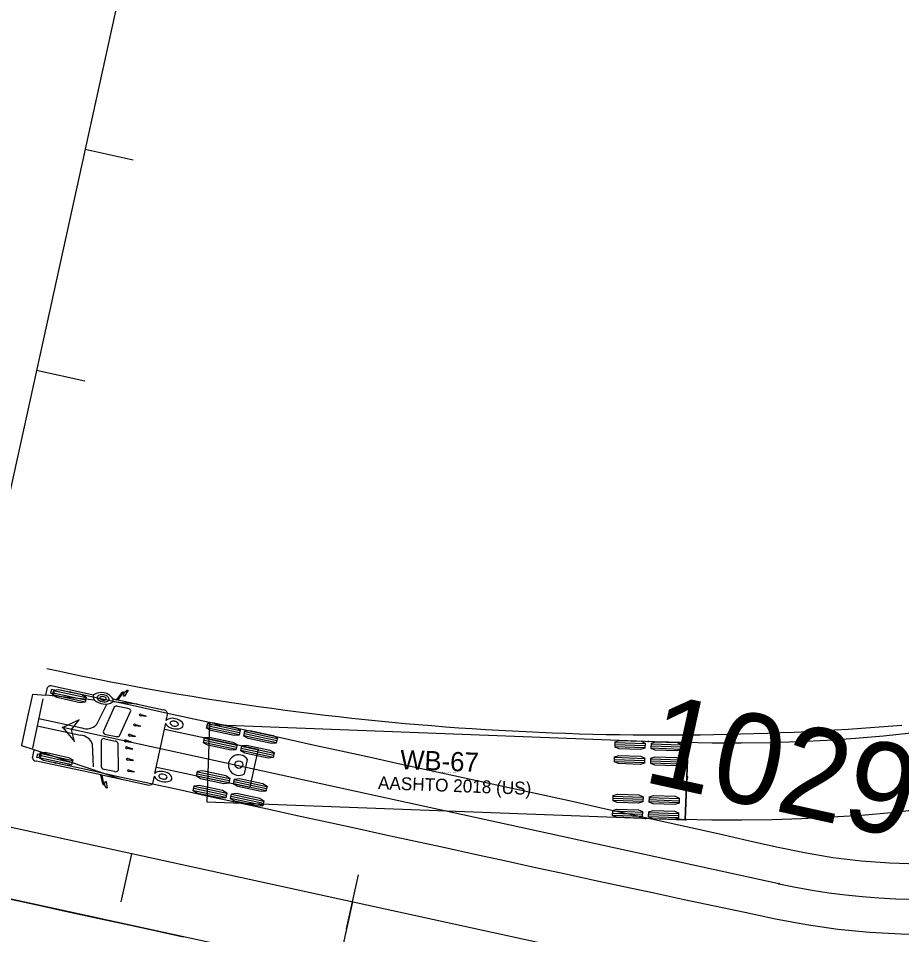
# Model space of a CAD drawing. Extents: x -69 to 14108008, y -6 to 8640172.
# Drawn here: x 14107666.4 to 14107764, y 8639454 to 8639555.2 of the extents above; entities that cross this region are included whole.
import ezdxf

# ---------------------------------------------------------------- set-up
doc = ezdxf.new("R2010")
doc.units = 0
for name, color, linetype in [('Alignment', 7, 'Continuous'), ('AutoTurn', 7, 'Continuous'), ('AutoTurn1', 7, 'Continuous'), ('TextAlignmentLrg', 7, 'Continuous'), ('TextAlignmentSml', 7, 'Continuous')]:
    doc.layers.add(name, color=color, linetype=linetype)

msp = doc.modelspace()

# ---------------------------------------------------------------- linework, layer by layer
at = {"layer": 'Alignment'}
for p, q in [((14107732.61, 8639808.61), (14107547.95, 8638968.47)), ((14107858.63, 8639423.72), (14107657.65, 8639467.55))]:
    msp.add_line(p, q, dxfattribs=at)
msp.add_arc((14107737.69, 8639796.04), 320, 257.6983, 274.7091, dxfattribs=at)
msp.add_arc((14107737.69, 8639796.04), 320, 257.6983, 274.7091, dxfattribs=at)
at = {"layer": 'AutoTurn'}
msp.add_line((14107750.39, 8639459.61), (14107671.27, 8639476.86), dxfattribs=at)
for points in [[(14107652.37, 8639452.09), (14107652.36, 8639452.07), (14107652.43, 8639452.05), (14107657.97, 8639450.85), (14107704.08, 8639440.79), (14107704.98, 8639444.94), (14107705.89, 8639449.1), (14107659.78, 8639459.15), (14107654.24, 8639460.36), (14107654.17, 8639460.37), (14107654.17, 8639460.35)], [(14107665.02, 8639458.01), (14107668.28, 8639457.3), (14107671.54, 8639456.59), (14107674.79, 8639455.88), (14107678.05, 8639455.17), (14107681.31, 8639454.46), (14107684.57, 8639453.75)]]:
    msp.add_lwpolyline(points, dxfattribs=at)
msp.add_arc((14107766.37, 8639532.88), 75, 257.6983, 348.2294, dxfattribs=at)
at = {"layer": 'AutoTurn1'}
for p, q in [((14107670.02, 8639481.05), (14107669.94, 8639480.65)), ((14107669.94, 8639480.65), (14107670.29, 8639480.58)), ((14107670.37, 8639480.98), (14107670.02, 8639481.05)), ((14107670.15, 8639481.45), (14107674.69, 8639480.48)), ((14107670.22, 8639480.71), (14107673.8, 8639479.93)), ((14107670.27, 8639480.94), (14107673.85, 8639480.16)), ((14107670.29, 8639480.58), (14107670.37, 8639480.98)), ((14107678.05, 8639480.69), (14107678.06, 8639480.71)), ((14107678.06, 8639480.71), (14107678.08, 8639480.73)), ((14107669.08, 8639480.02), (14107667.92, 8639474.58)), ((14107674.8, 8639479.9), (14107669.4, 8639480.42)), ((14107670.17, 8639480.49), (14107673.75, 8639479.71)), ((14107679.55, 8639479.44), (14107676.76, 8639479.71)), ((14107677.35, 8639479.91), (14107677.25, 8639479.93)), ((14107674.99, 8639477.16), (14107676.13, 8639479.45)), ((14107676.97, 8639479.11), (14107675.73, 8639476.38)), ((14107678.48, 8639478.96), (14107677.37, 8639479.2)), ((14107677.55, 8639475.95), (14107678.8, 8639478.69)), ((14107668.62, 8639477.85), (14107673.4, 8639476.83)), ((14107680.45, 8639478.07), (14107679.9, 8639478.14)), ((14107679.94, 8639478.31), (14107680.47, 8639478.15)), ((14107680.47, 8639478.15), (14107680.45, 8639478.07)), ((14107682.86, 8639478.45), (14107682.68, 8639477.63)), ((14107668.45, 8639477.04), (14107673.23, 8639476.02)), ((14107750.39, 8639459.61), (14107671.27, 8639476.86)), ((14107679.82, 8639476.96), (14107679.27, 8639477.03)), ((14107679.31, 8639477.2), (14107679.84, 8639477.04)), ((14107679.84, 8639477.04), (14107679.82, 8639476.96)), ((14107682.48, 8639476.68), (14107681.57, 8639472.45)), ((14107687.18, 8639476.85), (14107690.77, 8639476.08)), ((14107687.23, 8639477.07), (14107690.82, 8639476.31)), ((14107687.28, 8639477.3), (14107690.87, 8639476.53)), ((14107675.94, 8639475.6), (14107677.05, 8639475.36)), ((14107676.05, 8639476.1), (14107677.16, 8639475.87)), ((14107679.24, 8639475.84), (14107678.69, 8639475.91)), ((14107678.73, 8639476.08), (14107679.26, 8639475.92)), ((14107679.26, 8639475.92), (14107679.24, 8639475.84)), ((14107686.94, 8639475.68), (14107690.52, 8639474.92)), ((14107691.29, 8639475.97), (14107694.88, 8639475.21)), ((14107691.34, 8639476.2), (14107694.93, 8639475.43)), ((14107691.39, 8639476.42), (14107694.97, 8639475.65)), ((14107674.54, 8639475.07), (14107674.64, 8639472.52)), ((14107675.56, 8639472.48), (14107675.54, 8639475.48)), ((14107677.38, 8639475.12), (14107677.39, 8639472.12)), ((14107678.79, 8639475.21), (14107678.24, 8639475.29)), ((14107678.28, 8639475.45), (14107678.81, 8639475.3)), ((14107678.43, 8639474.69), (14107678.96, 8639474.54)), ((14107678.81, 8639475.3), (14107678.79, 8639475.21)), ((14107686.84, 8639475.24), (14107690.43, 8639474.47)), ((14107686.89, 8639475.46), (14107690.47, 8639474.69)), ((14107691, 8639474.58), (14107694.58, 8639473.82)), ((14107691.04, 8639474.81), (14107694.63, 8639474.04)), ((14107732.29, 8639474.76), (14107735.59, 8639474.64)), ((14107732.3, 8639474.99), (14107735.6, 8639474.87)), ((14107732.31, 8639475.22), (14107735.61, 8639475.09)), ((14107736.29, 8639474.61), (14107739.59, 8639474.48)), ((14107736.3, 8639474.84), (14107739.6, 8639474.71)), ((14107736.31, 8639475.07), (14107739.61, 8639474.94)), ((14107740.32, 8639475.14), (14107740, 8639466.65)), ((14107677.78, 8639471.13), (14107668.11, 8639474.38)), ((14107668.42, 8639473.54), (14107668.51, 8639473.95)), ((14107668.51, 8639473.95), (14107668.85, 8639473.87)), ((14107668.69, 8639473.56), (14107672.27, 8639472.78)), ((14107668.74, 8639473.79), (14107672.32, 8639473.01)), ((14107668.85, 8639473.87), (14107668.77, 8639473.47)), ((14107668.79, 8639474.01), (14107672.37, 8639473.23)), ((14107678.94, 8639474.45), (14107678.4, 8639474.53)), ((14107678.96, 8639474.54), (14107678.94, 8639474.45)), ((14107690.95, 8639474.36), (14107694.53, 8639473.59)), ((14107732.25, 8639473.57), (14107735.55, 8639473.45)), ((14107668.77, 8639473.47), (14107668.42, 8639473.54)), ((14107679.02, 8639473.19), (14107678.44, 8639473.27)), ((14107678.48, 8639473.44), (14107679.03, 8639473.28)), ((14107679.03, 8639473.28), (14107679.02, 8639473.19)), ((14107691.34, 8639471.75), (14107691.68, 8639473.33)), ((14107732.23, 8639473.11), (14107735.53, 8639472.99)), ((14107732.24, 8639473.34), (14107735.54, 8639473.22)), ((14107736.23, 8639472.96), (14107739.53, 8639472.84)), ((14107736.24, 8639473.19), (14107739.54, 8639473.06)), ((14107736.25, 8639473.42), (14107739.54, 8639473.29)), ((14107675.58, 8639471.59), (14107675.48, 8639471.62)), ((14107676.99, 8639472), (14107675.88, 8639472.24)), ((14107679.14, 8639471.92), (14107678.59, 8639472)), ((14107678.63, 8639472.16), (14107679.16, 8639472.01)), ((14107679.16, 8639472.01), (14107679.14, 8639471.92)), ((14107686.05, 8639471.54), (14107689.64, 8639470.77)), ((14107686.1, 8639471.76), (14107689.68, 8639470.99)), ((14107686.15, 8639471.98), (14107689.73, 8639471.22)), ((14107675.9, 8639470.6), (14107675.89, 8639470.57)), ((14107675.89, 8639470.57), (14107675.9, 8639470.54)), ((14107681.37, 8639471.5), (14107681.2, 8639470.67)), ((14107690.16, 8639470.66), (14107693.74, 8639469.89)), ((14107690.21, 8639470.88), (14107693.79, 8639470.12)), ((14107690.25, 8639471.11), (14107693.84, 8639470.34)), ((14107740.23, 8639470.9), (14107740.16, 8639470.9)), ((14107740.22, 8639470.63), (14107740.21, 8639470.36)), ((14107740.22, 8639470.64), (14107740.24, 8639471.16)), ((14107740.25, 8639471.43), (14107740.24, 8639471.16)), ((14107685.71, 8639469.92), (14107689.29, 8639469.16)), ((14107685.75, 8639470.15), (14107689.34, 8639469.38)), ((14107685.8, 8639470.37), (14107689.39, 8639469.6)), ((14107689.81, 8639469.04), (14107693.4, 8639468.28)), ((14107689.86, 8639469.27), (14107693.45, 8639468.5)), ((14107689.91, 8639469.49), (14107693.49, 8639468.73)), ((14107732.07, 8639468.83), (14107735.37, 8639468.71)), ((14107732.08, 8639469.06), (14107735.38, 8639468.94)), ((14107732.09, 8639469.29), (14107735.38, 8639469.17)), ((14107736.07, 8639468.68), (14107739.36, 8639468.56)), ((14107736.08, 8639469.14), (14107739.38, 8639469.01)), ((14107736.08, 8639468.91), (14107739.37, 8639468.78)), ((14107732.02, 8639467.64), (14107735.32, 8639467.52)), ((14107736.02, 8639467.49), (14107739.32, 8639467.36)), ((14107732.01, 8639467.18), (14107735.3, 8639467.06)), ((14107732.02, 8639467.41), (14107735.31, 8639467.29)), ((14107736, 8639467.03), (14107739.3, 8639466.91)), ((14107736.01, 8639467.26), (14107739.31, 8639467.14))]:
    msp.add_line(p, q, dxfattribs=at)
for points in [[(14107667.93, 8639473.53), (14107668.11, 8639474.37), (14107668.11, 8639474.38), (14107666.75, 8639474.83), (14107666.76, 8639474.9), (14107667.36, 8639477.7), (14107667.96, 8639480.5), (14107667.97, 8639480.56), (14107669.4, 8639480.42), (14107669.4, 8639480.43), (14107669.58, 8639481.27)], [(14107765.78, 8639461.78), (14107762.62, 8639461.87), (14107759.47, 8639462.11), (14107756.34, 8639462.48), (14107753.22, 8639463), (14107750.13, 8639463.65), (14107747, 8639464.36), (14107743.84, 8639465.07), (14107740.67, 8639465.78), (14107737.49, 8639466.49), (14107734.3, 8639467.19), (14107731.1, 8639467.89), (14107727.88, 8639468.6), (14107724.67, 8639469.3), (14107721.44, 8639470.01), (14107718.21, 8639470.71), (14107714.98, 8639471.42), (14107711.74, 8639472.13), (14107708.5, 8639472.83), (14107705.26, 8639473.54), (14107702.02, 8639474.25), (14107698.77, 8639474.96), (14107695.52, 8639475.67), (14107692.27, 8639476.37), (14107689.02, 8639477.08), (14107685.77, 8639477.79), (14107682.52, 8639478.5), (14107679.27, 8639479.21), (14107676.01, 8639479.92), (14107672.76, 8639480.63), (14107672.11, 8639480.77)], [(14107676.83, 8639480.02), (14107677.25, 8639479.93), (14107677.26, 8639479.94), (14107677.85, 8639480.74)], [(14107677.99, 8639480.75), (14107678.08, 8639480.73), (14107678.08, 8639480.73), (14107678.38, 8639481), (14107678.38, 8639481), (14107678.5, 8639480.97), (14107678.5, 8639480.97), (14107678.1, 8639480.32), (14107678, 8639480.34), (14107678.05, 8639480.69), (14107678.05, 8639480.69), (14107677.97, 8639480.7), (14107677.97, 8639480.7), (14107677.97, 8639480.7), (14107677.93, 8639480.7), (14107677.93, 8639480.7), (14107677.35, 8639479.91), (14107682.41, 8639478.83)], [(14107671.27, 8639476.86), (14107672.56, 8639475.33), (14107672.25, 8639476.65), (14107673.08, 8639477.71), (14107671.27, 8639476.86)], [(14107682.62, 8639477.35), (14107682.48, 8639476.68), (14107682.71, 8639476.63), (14107692.85, 8639474.47), (14107692.39, 8639472.35), (14107691.94, 8639470.23), (14107681.81, 8639472.4), (14107681.57, 8639472.45), (14107681.43, 8639471.77)], [(14107740.39, 8639475.12), (14107740.39, 8639475.14), (14107740.32, 8639475.14), (14107734.66, 8639475.36), (14107687.5, 8639477.15), (14107687.34, 8639472.9), (14107687.18, 8639468.66), (14107734.34, 8639466.87), (14107740, 8639466.65), (14107740.07, 8639466.65), (14107740.07, 8639466.67)], [(14107765.02, 8639476.24), (14107761.96, 8639475.9), (14107758.86, 8639475.63), (14107755.74, 8639475.43), (14107752.59, 8639475.27), (14107749.42, 8639475.18), (14107746.24, 8639475.13), (14107743.04, 8639475.14), (14107739.83, 8639475.19), (14107736.61, 8639475.29), (14107735.97, 8639475.31)], [(14107740.31, 8639471.16), (14107740.32, 8639471.42), (14107740.32, 8639471.42), (14107740.25, 8639471.43), (14107740.25, 8639471.46), (14107740.39, 8639475.09), (14107740.39, 8639475.1)], [(14107675.7, 8639470.63), (14107675.48, 8639471.61), (14107675.47, 8639471.62), (14107668.37, 8639473.13)], [(14107767.4, 8639453.99), (14107763.9, 8639454.03), (14107760.41, 8639454.21), (14107756.92, 8639454.56), (14107753.46, 8639455.05), (14107750.02, 8639455.7), (14107746.64, 8639456.41), (14107743.27, 8639457.12), (14107739.93, 8639457.83), (14107736.6, 8639458.55), (14107733.28, 8639459.26), (14107729.97, 8639459.98), (14107726.66, 8639460.7), (14107723.37, 8639461.41), (14107720.08, 8639462.13), (14107716.8, 8639462.84), (14107713.52, 8639463.56), (14107710.24, 8639464.27), (14107706.97, 8639464.98), (14107703.7, 8639465.69), (14107700.44, 8639466.41), (14107697.17, 8639467.12), (14107693.91, 8639467.83), (14107690.64, 8639468.54), (14107687.38, 8639469.25), (14107684.12, 8639469.96), (14107680.86, 8639470.68), (14107677.6, 8639471.39), (14107674.34, 8639472.1), (14107671.08, 8639472.81), (14107670.43, 8639472.95)], [(14107680.64, 8639470.51), (14107675.58, 8639471.59), (14107675.79, 8639470.63), (14107675.79, 8639470.63), (14107675.82, 8639470.61), (14107675.82, 8639470.61), (14107675.82, 8639470.61), (14107675.9, 8639470.6), (14107675.9, 8639470.6), (14107675.99, 8639470.93), (14107676.09, 8639470.91), (14107676.19, 8639470.16), (14107676.19, 8639470.15), (14107676.07, 8639470.18), (14107676.07, 8639470.18), (14107675.9, 8639470.54), (14107675.9, 8639470.54), (14107675.82, 8639470.56)], [(14107740.07, 8639466.69), (14107740.07, 8639466.7), (14107740.21, 8639470.33), (14107740.21, 8639470.36), (14107740.28, 8639470.36), (14107740.28, 8639470.36), (14107740.29, 8639470.63)], [(14107766.04, 8639467.8), (14107762.79, 8639467.44), (14107759.52, 8639467.16), (14107756.23, 8639466.94), (14107752.93, 8639466.78), (14107749.62, 8639466.68), (14107746.3, 8639466.63), (14107742.97, 8639466.64), (14107739.64, 8639466.69), (14107736.31, 8639466.79), (14107735.65, 8639466.82)]]:
    msp.add_lwpolyline(points, dxfattribs=at)
for points in [[(14107670.16, 8639480.43), (14107670.28, 8639480.99), (14107670.82, 8639481.05), (14107673.4, 8639480.49), (14107673.86, 8639480.21), (14107673.74, 8639479.65), (14107673.2, 8639479.59), (14107670.62, 8639480.16)], [(14107671.27, 8639476.86), (14107672.56, 8639475.33), (14107672.25, 8639476.65), (14107673.08, 8639477.71)], [(14107687.17, 8639476.79), (14107687.29, 8639477.35), (14107687.83, 8639477.41), (14107690.41, 8639476.86), (14107690.88, 8639476.59), (14107690.76, 8639476.03), (14107690.22, 8639475.97), (14107687.64, 8639476.52)], [(14107686.83, 8639475.18), (14107686.95, 8639475.74), (14107687.49, 8639475.8), (14107690.07, 8639475.25), (14107690.53, 8639474.97), (14107690.41, 8639474.41), (14107689.88, 8639474.35), (14107687.29, 8639474.9)], [(14107691.28, 8639475.92), (14107691.4, 8639476.48), (14107691.94, 8639476.54), (14107694.52, 8639475.99), (14107694.99, 8639475.71), (14107694.87, 8639475.15), (14107694.33, 8639475.09), (14107691.75, 8639475.64)], [(14107690.94, 8639474.3), (14107691.06, 8639474.86), (14107691.59, 8639474.92), (14107694.17, 8639474.37), (14107694.64, 8639474.1), (14107694.52, 8639473.54), (14107693.98, 8639473.48), (14107691.4, 8639474.03)], [(14107732.29, 8639474.7), (14107732.31, 8639475.28), (14107732.78, 8639475.43), (14107735.16, 8639475.34), (14107735.61, 8639475.15), (14107735.59, 8639474.58), (14107735.12, 8639474.42), (14107732.75, 8639474.52)], [(14107736.29, 8639474.55), (14107736.31, 8639475.12), (14107736.78, 8639475.28), (14107739.15, 8639475.19), (14107739.61, 8639475), (14107739.59, 8639474.43), (14107739.12, 8639474.27), (14107736.74, 8639474.36)], [(14107668.68, 8639473.51), (14107668.8, 8639474.07), (14107669.34, 8639474.13), (14107671.92, 8639473.56), (14107672.38, 8639473.29), (14107672.26, 8639472.73), (14107671.72, 8639472.67), (14107669.14, 8639473.23)], [(14107732.23, 8639473.06), (14107732.25, 8639473.63), (14107732.72, 8639473.78), (14107735.09, 8639473.69), (14107735.55, 8639473.5), (14107735.53, 8639472.93), (14107735.06, 8639472.78), (14107732.68, 8639472.87)], [(14107736.23, 8639472.9), (14107736.25, 8639473.48), (14107736.72, 8639473.63), (14107739.09, 8639473.54), (14107739.55, 8639473.35), (14107739.52, 8639472.78), (14107739.06, 8639472.62), (14107736.68, 8639472.71)], [(14107686.04, 8639471.48), (14107686.16, 8639472.04), (14107686.7, 8639472.1), (14107689.28, 8639471.55), (14107689.74, 8639471.27), (14107689.62, 8639470.71), (14107689.09, 8639470.65), (14107686.5, 8639471.2)], [(14107690.15, 8639470.6), (14107690.26, 8639471.16), (14107690.8, 8639471.22), (14107693.38, 8639470.67), (14107693.85, 8639470.4), (14107693.73, 8639469.84), (14107693.19, 8639469.78), (14107690.61, 8639470.33)], [(14107685.69, 8639469.87), (14107685.81, 8639470.43), (14107686.35, 8639470.49), (14107688.93, 8639469.94), (14107689.4, 8639469.66), (14107689.28, 8639469.1), (14107688.74, 8639469.04), (14107686.16, 8639469.59)], [(14107689.8, 8639468.99), (14107689.92, 8639469.55), (14107690.46, 8639469.61), (14107693.04, 8639469.06), (14107693.51, 8639468.78), (14107693.39, 8639468.22), (14107692.85, 8639468.16), (14107690.27, 8639468.71)], [(14107732.07, 8639468.78), (14107732.09, 8639469.35), (14107732.56, 8639469.5), (14107734.93, 8639469.41), (14107735.39, 8639469.22), (14107735.36, 8639468.65), (14107734.9, 8639468.5), (14107732.52, 8639468.59)], [(14107736.06, 8639468.62), (14107736.09, 8639469.2), (14107736.55, 8639469.35), (14107738.93, 8639469.26), (14107739.38, 8639469.07), (14107739.36, 8639468.5), (14107738.89, 8639468.34), (14107736.52, 8639468.43)], [(14107732, 8639467.13), (14107732.03, 8639467.7), (14107732.49, 8639467.85), (14107734.87, 8639467.76), (14107735.32, 8639467.57), (14107735.3, 8639467), (14107734.83, 8639466.85), (14107732.46, 8639466.94)], [(14107736, 8639466.98), (14107736.02, 8639467.55), (14107736.49, 8639467.7), (14107738.87, 8639467.61), (14107739.32, 8639467.42), (14107739.3, 8639466.85), (14107738.83, 8639466.7), (14107736.46, 8639466.79)]]:
    msp.add_lwpolyline(points, close=True, dxfattribs=at)
for centre, radius in [((14107672.11, 8639480.77), 0.0417), ((14107671.27, 8639476.86), 0.0417), ((14107735.97, 8639475.31), 0.0417), ((14107740.43, 8639475.11), 0.0266), ((14107670.43, 8639472.95), 0.0417), ((14107690.73, 8639472.77), 0.424), ((14107735.65, 8639466.82), 0.0417), ((14107740.11, 8639466.68), 0.0266), ((14107750.39, 8639459.61), 0.0417), ((14107750.39, 8639459.61), 0.0417)]:
    msp.add_circle(centre, radius, dxfattribs=at)
for centre, radius, start, end in [((14107766.37, 8639532.88), 75, 257.6983, 348.2294), ((14107669.98, 8639480.99), 0.486, 69.5324, 145.4835), ((14107675.53, 8639479.2), 1.53, 32.4392, 123.4482), ((14107677.91, 8639480.74), 0.0522, 76.829, 181.6837), ((14107677.91, 8639480.68), 0.108, 40.9228, 87.1053), ((14107675.06, 8639480.23), 0.425, 146.0094, 232.5457), ((14107675.94, 8639481.16), 1.7, 227.8671, 263.7752), ((14107675.58, 8639479.87), 0.634, 68.5303, 144.532), ((14107675.43, 8639480.21), 0.366, 175.9988, 248.4798), ((14107675.9, 8639480.89), 1.19, 239.0776, 274.967), ((14107675.59, 8639480.07), 0.223, 85.1813, 154.7838), ((14107675.54, 8639480.15), 0.158, 172.9177, 234.4304), ((14107675.81, 8639480.46), 0.575, 231.0216, 267.5919), ((14107675.65, 8639479.7), 0.589, 50.702, 93.6847), ((14107676.02, 8639480.57), 1.14, 256.651, 310.4535), ((14107675.85, 8639480.15), 0.263, 256.8813, 330.7833), ((14107675.62, 8639479.45), 1.03, 50.7701, 79.1566), ((14107676.01, 8639480.14), 0.44, 269.7407, 333.5535), ((14107675.91, 8639480.03), 0.17, 355.6155, 49.6798), ((14107676.09, 8639479.98), 0.317, 353.7966, 55.389), ((14107676.49, 8639479.93), 0.347, 320.2736, 15.0842), ((14107677.24, 8639478.83), 0.387, 70.3816, 133.6136), ((14107678.47, 8639478.63), 0.332, 10.603, 89.025), ((14107682.28, 8639478.22), 0.619, 22.1067, 77.9485), ((14107679.86, 8639478.18), 0.157, 57.2908, 144.4005), ((14107679.9, 8639478.33), 0.184, 199.1012, 270.9933), ((14107683.39, 8639476.74), 1.14, 73.5252, 128.3165), ((14107683.46, 8639476.43), 1.42, 42.9504, 80.0183), ((14107673.93, 8639478.25), 1.52, 249.5265, 313.9539), ((14107679.22, 8639477.07), 0.157, 57.2908, 144.4005), ((14107679.27, 8639477.22), 0.184, 199.1012, 270.9933), ((14107683.31, 8639477.6), 0.729, 199.624, 242.1379), ((14107683.85, 8639478.44), 1.73, 239.3213, 264.1198), ((14107683.31, 8639477.35), 0.169, 129.3934, 229.5121), ((14107683.71, 8639477.75), 0.732, 226.5382, 272.7726), ((14107683.49, 8639477.04), 0.522, 75.7769, 122.9411), ((14107683.54, 8639476.88), 0.664, 44.8209, 83.0426), ((14107683.86, 8639477.84), 1.14, 260.6617, 302.1825), ((14107683.78, 8639477.38), 0.362, 264.6089, 313.6499), ((14107683.89, 8639477.23), 0.172, 320.4942, 47.6448), ((14107684.25, 8639477.15), 0.346, 307.5407, 44.5537), ((14107673.13, 8639474.5), 1.52, 21.939, 86.3664), ((14107675.8, 8639475.34), 0.296, 60.93, 151.2277), ((14107676.03, 8639476.4), 0.296, 184.6652, 274.9629), ((14107677.29, 8639476.23), 0.387, 250.3841, 313.6111), ((14107678.64, 8639475.94), 0.157, 57.2908, 144.4005), ((14107678.69, 8639476.1), 0.184, 199.1012, 270.9933), ((14107677.02, 8639474.98), 0.387, 22.2817, 85.5088), ((14107678.19, 8639475.32), 0.157, 57.2908, 144.4005), ((14107678.22, 8639475.44), 0.157, 191.4924, 278.6021), ((14107678.35, 8639474.53), 0.184, 64.8996, 136.7916), ((14107678.37, 8639474.69), 0.157, 191.4924, 278.6021), ((14107742.41, 8639475.04), 2.02, 177.8272, 178.511), ((14107690.72, 8639472.71), 1.14, 32.9464, 302.9464), ((14107668.4, 8639473.62), 0.486, 190.4094, 266.3605), ((14107678.43, 8639473.27), 0.184, 64.8996, 136.7916), ((14107678.45, 8639473.42), 0.157, 191.4924, 278.6021), ((14107675.91, 8639472.62), 0.387, 202.2793, 265.5113), ((14107677.12, 8639472.31), 0.332, 246.8678, 325.2898), ((14107678.55, 8639472), 0.184, 64.8996, 136.7916), ((14107678.57, 8639472.15), 0.157, 191.4924, 278.6021), ((14107681.96, 8639471.27), 0.729, 93.7549, 136.2689), ((14107682.06, 8639471.5), 0.169, 106.3808, 206.4995), ((14107682.11, 8639470.28), 1.73, 71.7731, 96.5716), ((14107682.26, 8639470.97), 0.732, 63.1203, 109.3547), ((14107682.47, 8639471.28), 0.362, 22.243, 71.284), ((14107682.36, 8639470.82), 1.14, 33.7104, 75.2311), ((14107675.74, 8639470.61), 0.0522, 154.2092, 259.0638), ((14107675.77, 8639470.66), 0.108, 248.7876, 294.9701), ((14107680.77, 8639471.12), 0.619, 257.9444, 313.7861), ((14107682.38, 8639472.02), 1.14, 207.5764, 262.3677), ((14107682.35, 8639471.71), 0.522, 212.9518, 260.1159), ((14107682.57, 8639472.27), 1.42, 255.8746, 292.9424), ((14107682.46, 8639471.83), 0.664, 252.8503, 291.072), ((14107682.64, 8639471.37), 0.172, 288.248, 15.3986), ((14107683, 8639471.29), 0.346, 291.3391, 28.3522), ((14107740.26, 8639470.63), 0.0352, 357.8525, 176.8529), ((14107740.26, 8639470.63), 0.0353, 181.1634, 359.5131), ((14107740.28, 8639471.16), 0.0354, 2.1188, 174.3042), ((14107740.28, 8639471.16), 0.0352, 178.8016, 357.802), ((14107740.11, 8639466.68), 0.0363, 196.9047, 158.066)]:
    msp.add_arc(centre, radius, start, end, dxfattribs=at)
for centre, major_axis, start_param, end_param in [((14107677.92, 8639480.74), (-0.0765, 0.0163), 0.569648, 1.840391), ((14107677.92, 8639480.74), (-0.0765, 0.0163), 2.398717, 3.668019), ((14107675.76, 8639470.6), (0.0765, -0.0163), 1.301202, 2.571945), ((14107675.76, 8639470.6), (-0.0765, 0.0163), 2.615166, 3.884468)]:
    msp.add_ellipse(centre, major_axis=major_axis, ratio=0.544872, start_param=start_param, end_param=end_param, dxfattribs=at)
at = {"layer": 'TextAlignmentLrg'}
msp.add_line((14107703.29, 8639457.6), (14107702.12, 8639452.26), dxfattribs=at)
at = {"layer": 'TextAlignmentSml'}
for p, q in [((14107673.74, 8639540.75), (14107679.07, 8639539.58)), ((14107668.37, 8639516.34), (14107673.7, 8639515.16)), ((14107678.86, 8639462.92), (14107677.7, 8639457.59)), ((14107702.63, 8639454.61), (14107703.94, 8639460.59))]:
    msp.add_line(p, q, dxfattribs=at)

# ---------------------------------------------------------------- texts
at = {"layer": 'AutoTurn1'}
for s, height, p in [('WB-67', 2.125, (14107708.52, 8639472.27)), ('(c) 2023 Transoft Solutions, Inc. All rights reserved.', 0.085, (14107712.08, 8639471.92)), ('AASHTO 2018 (US)', 1.4167, (14107706.08, 8639470.06))]:
    msp.add_text(s, height=height, rotation=357.8272, dxfattribs=at).set_placement(p)
at = {"layer": 'TextAlignmentLrg'}
msp.add_text('10295+00', height=10.02, rotation=347.6032, dxfattribs=at).set_placement((14107735.18, 8639470.92))
at = {"layer": 'TextAlignmentSml'}
msp.add_text('10295+00', height=10.02, rotation=347.6032, dxfattribs=at).set_placement((14107735.18, 8639470.92))

doc.saveas('drawing.dxf')
